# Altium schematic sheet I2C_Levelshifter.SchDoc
size A4
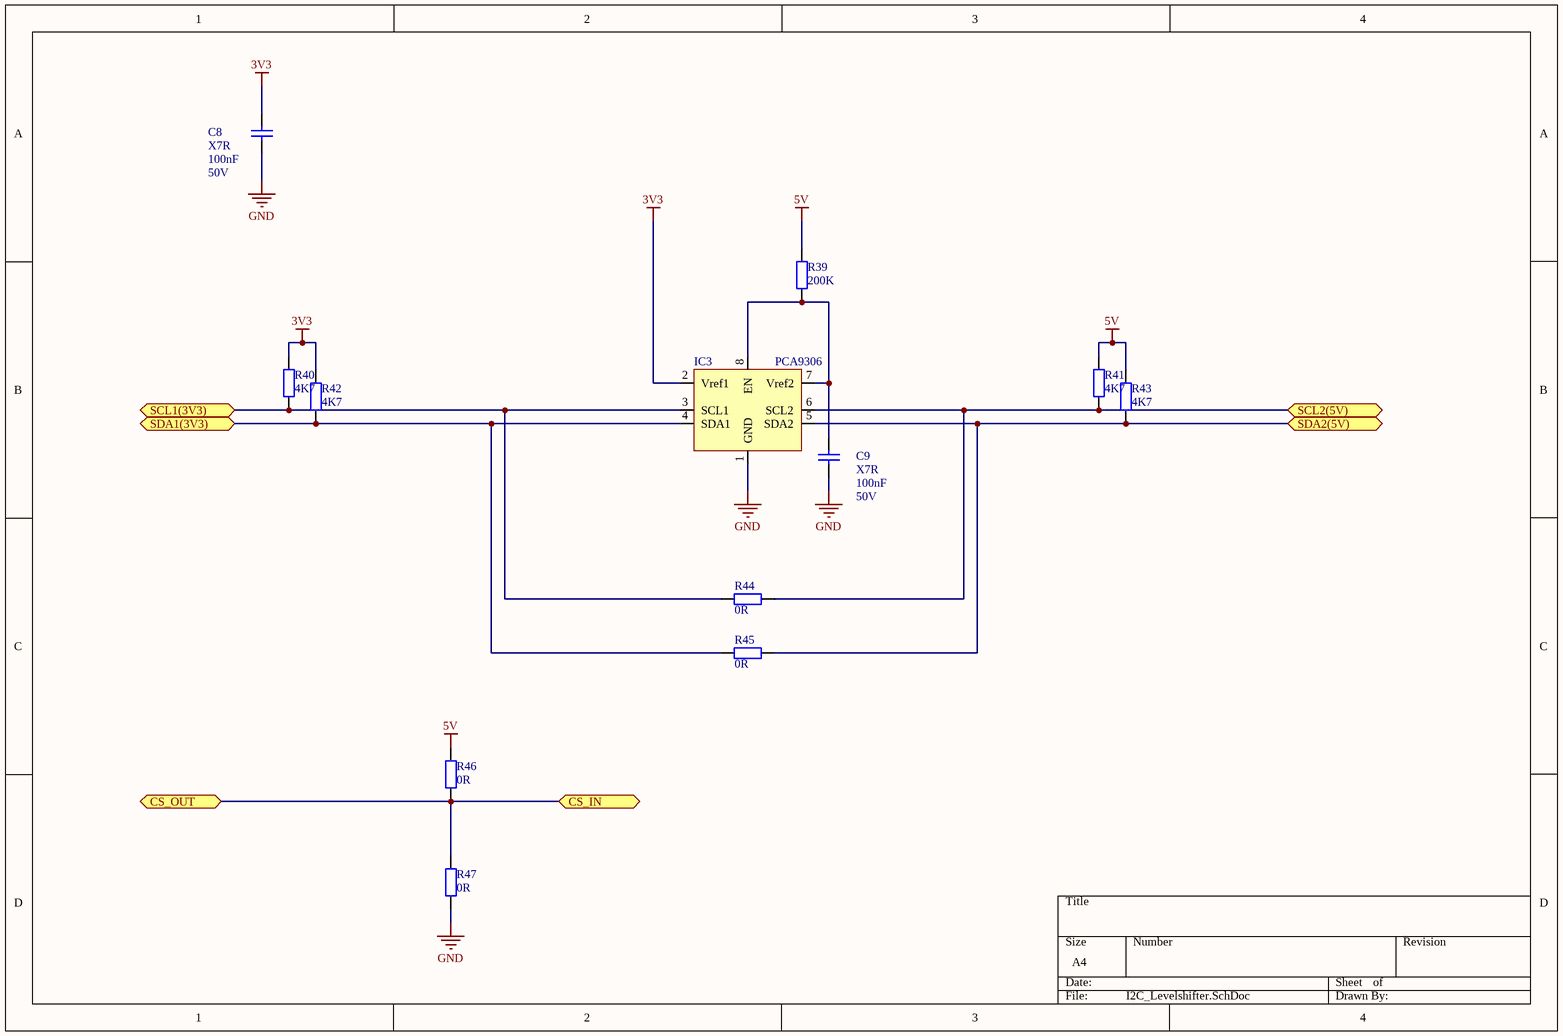
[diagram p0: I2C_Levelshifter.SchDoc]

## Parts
C8  A_Charakteristik: X7R  L_Spannung: 50V  [RLCDT_0805]  (hidden comment: 100nF)
C9  A_Charakteristik: X7R  L_Spannung: 50V  [RLCDT_0805]  (hidden comment: 100nF)
IC3  PCA9306  [SM8]
R39  200K  [RLCDT_0805]
R40  4K7  [RLCDT_0805]
R41  4K7  [RLCDT_0805]
R42  4K7  [RLCDT_0805]
R43  4K7  [RLCDT_0805]
R44  0R  [RLCDT_0805]
R45  0R  [RLCDT_0805]
R46  0R  [RLCDT_0805]
R47  0R  [RLCDT_0805]

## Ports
CS_IN, CS_OUT, SCL1(3V3), SCL2(5V), SDA1(3V3), SDA2(5V)

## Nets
3V3: C8.1 IC3.2(Vref1) R40.2 R42.2
5V: R39.2 R41.2 R43.2 R46.2
GND: C8.2 C9.2 IC3.1(GND) R47.1
CS_IN: R46.1 R47.2 ; port CS_OUT, port CS_IN
SCL1(3V3): IC3.3(SCL1) R40.1 R44.2 ; port SCL1(3V3)
SCL2(5V): IC3.6(SCL2) R41.1 R44.1 ; port SCL2(5V)
SDA1(3V3): IC3.4(SDA1) R42.1 R45.2 ; port SDA1(3V3)
SDA2(5V): IC3.5(SDA2) R43.1 R45.1 ; port SDA2(5V)
NetC9_1: C9.1 IC3.7(Vref2) IC3.8(EN) R39.1

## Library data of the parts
C8 C9 = C_KERAMIK: Kondensator, Keramik; W_Erstellt: MRipel; A_Wichtiger_Hinweis: optional; H_Temp_min: ?°C; J_Richtpreis_10: 0,00; G_Wird_beigestellt: Nein; A_Update_From_DB: Ja; A_Database_ID: not updated
R39-R47 = R: Widerstand; W_Erstellt: MRipel; A_Wichtiger_Hinweis: optional; L_Spannung: 50V; H_Temp_min: ?°C; J_Richtpreis_10: 0,00; G_Wird_beigestellt: Nein; A_Update_From_DB: Ja; A_Database_ID: not updated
